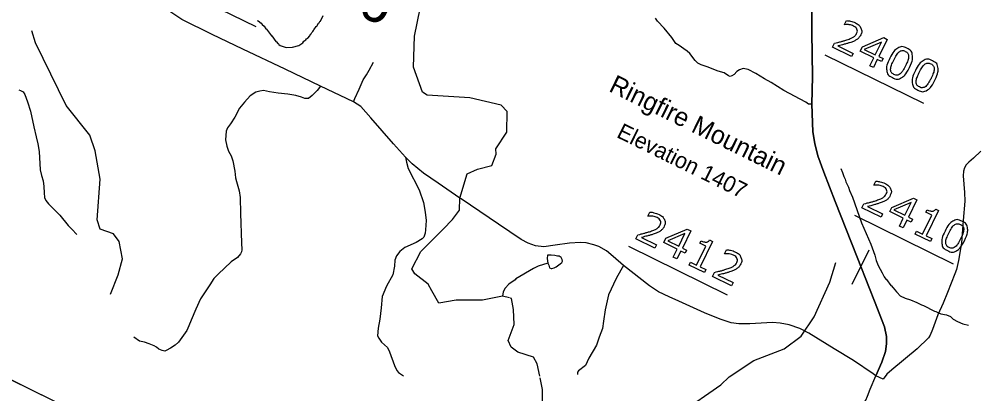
# Model space of a CAD drawing. Extents: x 1428428 to 1430511, y 857911 to 859585.
# Drawn here: x 1429036.9 to 1429265.4, y 859219.8 to 859309.5 of the extents above; entities that cross this region are included whole.
import ezdxf

# ---------------------------------------------------------------- set-up
doc = ezdxf.new("R2010")
doc.units = 0
for name, color, linetype in [('Default', 7, 'Continuous'), ('Exist Hydrographic Creek Single Shore', 7, 'Continuous'), ('Exist Hydrographic Misc Water Feature', 7, 'Continuous'), ('Exist Road Non-System Type 51', 7, 'Continuous'), ('Exist Road Secondary Type 51 Attributed', 7, 'Continuous'), ('Sheet Data Field CELL', 7, 'Continuous'), ('Sheet Title CELL', 7, 'Continuous')]:
    doc.layers.add(name, color=color, linetype=linetype)

msp = doc.modelspace()

# ---------------------------------------------------------------- linework, layer by layer
at = {"layer": 'Default'}
for p, q in [((1429069.85, 859319.28), (1429093.43, 859307.68)), ((1429229.5, 859300.92), (1429253.07, 859289.32)), ((1429236.58, 859262.53), (1429260.15, 859250.93)), ((1429182.53, 859255.12), (1429206.11, 859243.52)), ((1429239.98, 859254.23), (1429235.94, 859246.01))]:
    msp.add_line(p, q, dxfattribs=at)
for points in [[(1429234.21, 859308.12), (1429234.16, 859308.14), (1429234.63, 859309.09)], [(1429235.85, 859300.48), (1429231.29, 859302.72), (1429231.76, 859303.67)], [(1429232.61, 859303.04), (1429236.23, 859301.26), (1429235.85, 859300.48)], [(1429243.03, 859299.29), (1429242.03, 859299.79), (1429241.1, 859297.89), (1429240.23, 859298.32), (1429241.17, 859300.21), (1429237.94, 859301.8), (1429238.45, 859302.84), (1429243.58, 859305.03), (1429244.41, 859304.62), (1429242.39, 859300.51), (1429243.39, 859300.02), (1429243.03, 859299.29)], [(1429241.52, 859300.94), (1429243.02, 859303.98), (1429238.91, 859302.22), (1429241.52, 859300.94)], [(1429241.28, 859269.73), (1429241.23, 859269.75), (1429241.7, 859270.7)], [(1429250.1, 859260.9), (1429249.1, 859261.39), (1429248.17, 859259.5), (1429247.3, 859259.92), (1429248.24, 859261.82), (1429245.01, 859263.41), (1429245.52, 859264.44), (1429250.65, 859266.64), (1429251.48, 859266.23), (1429249.46, 859262.12), (1429250.46, 859261.63), (1429250.1, 859260.9)], [(1429242.92, 859262.08), (1429238.36, 859264.32), (1429238.83, 859265.28)], [(1429239.68, 859264.64), (1429243.3, 859262.86), (1429242.92, 859262.08)], [(1429248.59, 859262.54), (1429250.09, 859265.58), (1429245.98, 859263.83), (1429248.59, 859262.54)], [(1429187.24, 859262.32), (1429187.19, 859262.34), (1429187.66, 859263.29)], [(1429254.73, 859256.27), (1429251.09, 859258.06), (1429251.43, 859258.75), (1429252.83, 859258.06), (1429255.05, 859262.57), (1429253.65, 859263.26), (1429253.95, 859263.87)], [(1429255.98, 859264.04), (1429256.68, 859263.7), (1429253.7, 859257.63), (1429255.07, 859256.96), (1429254.73, 859256.27)], [(1429188.88, 859254.67), (1429184.32, 859256.92), (1429184.79, 859257.87)], [(1429196.06, 859253.49), (1429195.06, 859253.98), (1429194.13, 859252.09), (1429193.26, 859252.51), (1429194.19, 859254.41), (1429190.97, 859256), (1429191.48, 859257.04), (1429196.61, 859259.23), (1429197.44, 859258.82), (1429195.42, 859254.71), (1429196.42, 859254.22), (1429196.06, 859253.49)], [(1429194.55, 859255.14), (1429196.05, 859258.17), (1429191.94, 859256.42), (1429194.55, 859255.14)], [(1429185.64, 859257.24), (1429189.26, 859255.45), (1429188.88, 859254.67)], [(1429200.69, 859248.86), (1429197.05, 859250.65), (1429197.39, 859251.34), (1429198.79, 859250.65), (1429201.01, 859255.16), (1429199.6, 859255.85), (1429199.91, 859256.46)], [(1429201.94, 859256.63), (1429202.64, 859256.29), (1429199.65, 859250.22), (1429201.03, 859249.55), (1429200.69, 859248.86)], [(1429205.53, 859253.31), (1429205.49, 859253.34), (1429205.95, 859254.28)], [(1429207.17, 859245.67), (1429202.61, 859247.91), (1429203.08, 859248.87)], [(1429203.93, 859248.23), (1429207.56, 859246.45), (1429207.17, 859245.67)]]:
    msp.add_lwpolyline(points, dxfattribs=at)
for points in [[(1429231.76, 859303.67), (1429232.43, 859303.84), (1429233.11, 859304.01), (1429233.79, 859304.19), (1429234.4, 859304.39), (1429235.68, 859304.8), (1429236.25, 859305.13), (1429236.81, 859305.47), (1429237.09, 859306.04), (1429237.35, 859306.57), (1429237.15, 859307.03), (1429236.95, 859307.5), (1429236.33, 859307.81), (1429235.92, 859308.01), (1429235.36, 859308.1), (1429234.81, 859308.19), (1429234.21, 859308.12)], [(1429234.63, 859309.09), (1429235.03, 859309.09), (1429235.63, 859308.96), (1429236.23, 859308.82), (1429236.73, 859308.58), (1429237.77, 859308.07), (1429238.11, 859307.28), (1429238.45, 859306.49), (1429238.03, 859305.64), (1429237.84, 859305.25), (1429237.58, 859304.97), (1429237.32, 859304.68), (1429236.99, 859304.48), (1429236.67, 859304.29), (1429236.3, 859304.13), (1429235.93, 859303.98), (1429235.43, 859303.82), (1429234.71, 859303.58), (1429233.98, 859303.39), (1429233.24, 859303.2), (1429232.61, 859303.04)], [(1429249.69, 859297.85), (1429248.8, 859296.03), (1429247.82, 859295.46), (1429246.83, 859294.89), (1429245.64, 859295.48), (1429244.43, 859296.08), (1429244.29, 859297.21), (1429244.16, 859298.35), (1429245.04, 859300.13), (1429245.92, 859301.93), (1429246.91, 859302.51), (1429247.89, 859303.09), (1429249.09, 859302.5), (1429250.3, 859301.9), (1429250.43, 859300.75), (1429250.56, 859299.61), (1429249.69, 859297.85)], [(1429247.49, 859296.38), (1429247.83, 859296.67), (1429248.13, 859297.14), (1429248.43, 859297.6), (1429248.78, 859298.3), (1429249.11, 859298.99), (1429249.31, 859299.52), (1429249.5, 859300.06), (1429249.51, 859300.49), (1429249.52, 859300.92), (1429249.34, 859301.23), (1429249.15, 859301.54), (1429248.72, 859301.75), (1429248.3, 859301.96), (1429247.93, 859301.92), (1429247.57, 859301.88), (1429247.23, 859301.6), (1429246.91, 859301.34), (1429246.59, 859300.83), (1429246.27, 859300.32), (1429245.95, 859299.68), (1429245.61, 859298.97), (1429245.42, 859298.47), (1429245.24, 859297.97), (1429245.22, 859297.52), (1429245.19, 859297.09), (1429245.37, 859296.77), (1429245.55, 859296.45), (1429246.01, 859296.23), (1429246.43, 859296.02), (1429246.8, 859296.06), (1429247.16, 859296.1), (1429247.49, 859296.38)], [(1429255.79, 859294.85), (1429254.9, 859293.03), (1429253.91, 859292.46), (1429252.93, 859291.89), (1429251.74, 859292.48), (1429250.53, 859293.08), (1429250.39, 859294.21), (1429250.26, 859295.34), (1429251.13, 859297.13), (1429252.02, 859298.92), (1429253.01, 859299.5), (1429253.99, 859300.08), (1429255.19, 859299.5), (1429256.4, 859298.9), (1429256.53, 859297.75), (1429256.66, 859296.61), (1429255.79, 859294.85)], [(1429253.59, 859293.38), (1429253.93, 859293.67), (1429254.23, 859294.13), (1429254.53, 859294.6), (1429254.87, 859295.3), (1429255.21, 859295.99), (1429255.41, 859296.52), (1429255.6, 859297.06), (1429255.61, 859297.49), (1429255.62, 859297.92), (1429255.44, 859298.23), (1429255.25, 859298.54), (1429254.82, 859298.75), (1429254.4, 859298.96), (1429254.03, 859298.92), (1429253.67, 859298.88), (1429253.33, 859298.6), (1429253.01, 859298.34), (1429252.69, 859297.83), (1429252.37, 859297.32), (1429252.05, 859296.68), (1429251.7, 859295.97), (1429251.52, 859295.47), (1429251.34, 859294.97), (1429251.31, 859294.52), (1429251.29, 859294.09), (1429251.47, 859293.77), (1429251.65, 859293.45), (1429252.1, 859293.23), (1429252.53, 859293.02), (1429252.9, 859293.06), (1429253.26, 859293.1), (1429253.59, 859293.38)], [(1429238.83, 859265.28), (1429239.5, 859265.45), (1429240.18, 859265.62), (1429240.86, 859265.79), (1429241.47, 859265.99), (1429242.75, 859266.4), (1429243.32, 859266.74), (1429243.88, 859267.08), (1429244.17, 859267.65), (1429244.42, 859268.17), (1429244.22, 859268.64), (1429244.02, 859269.11), (1429243.4, 859269.41), (1429242.99, 859269.62), (1429242.43, 859269.71), (1429241.88, 859269.8), (1429241.28, 859269.73)], [(1429241.7, 859270.7), (1429242.1, 859270.7), (1429242.7, 859270.56), (1429243.3, 859270.43), (1429243.8, 859270.18), (1429244.84, 859269.67), (1429245.18, 859268.88), (1429245.52, 859268.1), (1429245.1, 859267.24), (1429244.92, 859266.86), (1429244.65, 859266.57), (1429244.39, 859266.29), (1429244.06, 859266.09), (1429243.74, 859265.89), (1429243.37, 859265.74), (1429243, 859265.58), (1429242.5, 859265.42), (1429241.78, 859265.19), (1429241.05, 859264.99), (1429240.31, 859264.8), (1429239.68, 859264.64)], [(1429184.79, 859257.87), (1429185.46, 859258.04), (1429186.14, 859258.21), (1429186.82, 859258.38), (1429187.43, 859258.58), (1429188.71, 859258.99), (1429189.28, 859259.33), (1429189.84, 859259.67), (1429190.12, 859260.24), (1429190.38, 859260.77), (1429190.18, 859261.23), (1429189.98, 859261.7), (1429189.36, 859262), (1429188.94, 859262.21), (1429188.39, 859262.3), (1429187.84, 859262.39), (1429187.24, 859262.32)], [(1429187.66, 859263.29), (1429188.06, 859263.29), (1429188.66, 859263.15), (1429189.26, 859263.02), (1429189.76, 859262.77), (1429190.8, 859262.26), (1429191.14, 859261.48), (1429191.48, 859260.69), (1429191.06, 859259.83), (1429190.87, 859259.45), (1429190.61, 859259.17), (1429190.35, 859258.88), (1429190.01, 859258.68), (1429189.7, 859258.48), (1429189.33, 859258.33), (1429188.96, 859258.18), (1429188.46, 859258.01), (1429187.74, 859257.78), (1429187.01, 859257.59), (1429186.27, 859257.39), (1429185.64, 859257.24)], [(1429253.95, 859263.87), (1429254.23, 859263.73), (1429254.58, 859263.62), (1429254.93, 859263.51), (1429255.14, 859263.52), (1429255.41, 859263.53), (1429255.61, 859263.64), (1429255.82, 859263.76), (1429255.98, 859264.04)], [(1429262.86, 859256.45), (1429261.97, 859254.64), (1429260.99, 859254.07), (1429260, 859253.5), (1429258.81, 859254.09), (1429257.6, 859254.68), (1429257.46, 859255.82), (1429257.33, 859256.95), (1429258.21, 859258.73), (1429259.09, 859260.53), (1429260.08, 859261.11), (1429261.06, 859261.69), (1429262.26, 859261.1), (1429263.47, 859260.51), (1429263.6, 859259.36), (1429263.73, 859258.21), (1429262.86, 859256.45)], [(1429260.66, 859254.98), (1429261, 859255.27), (1429261.3, 859255.74), (1429261.6, 859256.21), (1429261.95, 859256.9), (1429262.28, 859257.59), (1429262.48, 859258.13), (1429262.67, 859258.66), (1429262.68, 859259.09), (1429262.69, 859259.52), (1429262.51, 859259.83), (1429262.32, 859260.14), (1429261.89, 859260.35), (1429261.47, 859260.56), (1429261.1, 859260.52), (1429260.74, 859260.48), (1429260.4, 859260.21), (1429260.08, 859259.95), (1429259.76, 859259.44), (1429259.44, 859258.92), (1429259.12, 859258.28), (1429258.78, 859257.58), (1429258.59, 859257.08), (1429258.41, 859256.58), (1429258.38, 859256.12), (1429258.36, 859255.7), (1429258.54, 859255.38), (1429258.72, 859255.06), (1429259.18, 859254.83), (1429259.6, 859254.62), (1429259.97, 859254.66), (1429260.33, 859254.7), (1429260.66, 859254.98)], [(1429199.91, 859256.46), (1429200.19, 859256.32), (1429200.54, 859256.21), (1429200.89, 859256.1), (1429201.1, 859256.11), (1429201.36, 859256.12), (1429201.57, 859256.23), (1429201.78, 859256.35), (1429201.94, 859256.63)], [(1429203.08, 859248.87), (1429203.76, 859249.04), (1429204.44, 859249.21), (1429205.11, 859249.38), (1429205.72, 859249.58), (1429207.01, 859249.99), (1429207.57, 859250.33), (1429208.14, 859250.66), (1429208.42, 859251.24), (1429208.68, 859251.76), (1429208.48, 859252.23), (1429208.27, 859252.7), (1429207.65, 859253), (1429207.24, 859253.2), (1429206.69, 859253.3), (1429206.14, 859253.39), (1429205.53, 859253.31)], [(1429205.95, 859254.28), (1429206.35, 859254.28), (1429206.95, 859254.15), (1429207.55, 859254.02), (1429208.06, 859253.77), (1429209.09, 859253.26), (1429209.44, 859252.47), (1429209.78, 859251.68), (1429209.36, 859250.83), (1429209.17, 859250.45), (1429208.91, 859250.16), (1429208.65, 859249.88), (1429208.31, 859249.67), (1429208, 859249.48), (1429207.63, 859249.33), (1429207.26, 859249.17), (1429206.75, 859249.01), (1429206.04, 859248.77), (1429205.3, 859248.58), (1429204.57, 859248.39), (1429203.93, 859248.23)]]:
    msp.add_open_spline(points, degree=3, dxfattribs=at)
at = {"layer": 'Exist Hydrographic Creek Single Shore'}
for points in [[(1429142.24, 859266.66), (1429143.99, 859272.42), (1429146.47, 859273.58), (1429149.91, 859274.45), (1429150.91, 859277.12), (1429150.87, 859278.47), (1429153.46, 859282.38), (1429153.58, 859287.34), (1429152.09, 859288.85), (1429144.6, 859290.66), (1429134.41, 859291.27), (1429133.27, 859292.01), (1429131.12, 859298), (1429131.37, 859305.4), (1429132.73, 859312.02), (1429138.15, 859322.52), (1429140.73, 859325.69), (1429140.77, 859325.72)], [(1429154.07, 859242.79), (1429152.45, 859243.17), (1429147.63, 859242.2), (1429141.36, 859242.24), (1429137.19, 859241.51), (1429135.57, 859244.48), (1429134.69, 859246.04), (1429131.45, 859248.53), (1429130.79, 859249.76), (1429132.93, 859253.9), (1429138.25, 859259.19), (1429140.45, 859261.56), (1429142.19, 859263.76), (1429142.24, 859266.66)], [(1429167.35, 859199.95), (1429161.59, 859203.67), (1429160.48, 859205.14), (1429160.01, 859208.63), (1429158.99, 859210.63), (1429161.98, 859217.51), (1429162.03, 859220.88), (1429161.44, 859223.64)]]:
    msp.add_lwpolyline(points, dxfattribs=at)
at = {"layer": 'Exist Hydrographic Misc Water Feature'}
for points in [[(1429093.77, 859309.16), (1429094.06, 859309.01), (1429094.77, 859308.46), (1429094.97, 859308.18), (1429095.47, 859307.74), (1429095.89, 859307.16), (1429096.03, 859307.09), (1429097.19, 859305.49), (1429097.33, 859305.42), (1429098.27, 859304.12), (1429098.41, 859304.04), (1429098.73, 859303.61), (1429098.87, 859303.54), (1429098.99, 859303.38), (1429099.32, 859303.17), (1429100.75, 859302.65), (1429102.26, 859302.77), (1429103.73, 859303.17), (1429104.67, 859303.77), (1429104.96, 859304.16), (1429105.39, 859304.47), (1429105.58, 859304.74), (1429105.9, 859304.93), (1429106.34, 859305.42), (1429106.56, 859305.85), (1429106.7, 859305.95), (1429106.87, 859306.27), (1429107.07, 859306.49), (1429107.22, 859306.77), (1429107.36, 859306.87), (1429107.87, 859307.69), (1429108.02, 859307.79), (1429108.46, 859308.47), (1429108.6, 859308.57), (1429108.75, 859308.86), (1429108.9, 859308.96), (1429109.59, 859310.3)], [(1429058.76, 859243.64), (1429060.59, 859248.31), (1429061.63, 859252.13), (1429060.77, 859256.27), (1429059.47, 859258.13), (1429056.27, 859259.19), (1429055.54, 859261.42), (1429056.26, 859271.17), (1429055.09, 859277.98), (1429053.81, 859281.68), (1429048.09, 859288.77), (1429040.83, 859303.76), (1429039.9, 859306.68)], [(1429233.29, 859273.73), (1429233.7, 859272.79), (1429234.01, 859271.82), (1429234.32, 859271.21), (1429234.53, 859270.56), (1429235.17, 859269.28), (1429235.42, 859268.47), (1429236.13, 859266.88), (1429238.23, 859260.7), (1429240.46, 859255.62), (1429241.4, 859253.04), (1429241.76, 859251.7), (1429242.23, 859250.51), (1429243.18, 859248.79), (1429243.63, 859247.84), (1429244.05, 859247.26), (1429244.19, 859247.19), (1429245.24, 859245.74), (1429245.39, 859245.66), (1429245.7, 859245.23), (1429245.84, 859245.16), (1429246.62, 859244.21), (1429246.77, 859244.09), (1429247.49, 859243.31), (1429248.7, 859242.68), (1429250, 859242.3), (1429251.44, 859241.71), (1429252.57, 859241.12), (1429253.04, 859240.97), (1429255.73, 859239.57), (1429256.05, 859239.49), (1429256.62, 859239.19), (1429257.22, 859238.97), (1429258.54, 859238.73), (1429259.5, 859238.33), (1429260.19, 859237.7), (1429261.2, 859237.11), (1429262.44, 859236.56), (1429263.81, 859236.27)], [(1429163.3, 859251.1), (1429163.49, 859250.65), (1429163.69, 859250.01), (1429164.04, 859249.82), (1429164.22, 859249.82), (1429164.78, 859249.94), (1429165.23, 859250.2), (1429166.24, 859250.93), (1429166.6, 859251.28), (1429166.75, 859251.57), (1429166.72, 859251.94), (1429166.48, 859252.43), (1429165.95, 859252.8), (1429165.59, 859252.8), (1429164.95, 859252.96), (1429164.09, 859253.04), (1429163.17, 859253), (1429163.08, 859252.21), (1429163.3, 859251.1)], [(1429163.3, 859251.1), (1429160.94, 859250.35), (1429159.86, 859249.83), (1429155.64, 859247.34), (1429155.42, 859247.09), (1429153.97, 859246.04), (1429153.03, 859245.09), (1429152.59, 859244.24), (1429152.45, 859243.17)], [(1429167.35, 859199.95), (1429168.85, 859202.13), (1429170.89, 859203.15), (1429172.46, 859203.3), (1429173.89, 859202.77), (1429177.99, 859203.09), (1429180.09, 859204.23), (1429188.61, 859212.38), (1429194.99, 859215.29), (1429204.63, 859221.98), (1429206.59, 859223.92), (1429212.53, 859227.8), (1429219.8, 859230.61), (1429223.81, 859233.64), (1429226.92, 859238.24), (1429230.66, 859246.57), (1429232.15, 859251.27)], [(1429161.34, 859224.1), (1429160.71, 859227.04), (1429159.83, 859228.6), (1429156.13, 859229.78), (1429154.5, 859230.99), (1429153.82, 859232.6), (1429155.25, 859236.38), (1429155.08, 859240.01), (1429154.58, 859242.66), (1429154.23, 859242.75)]]:
    msp.add_lwpolyline(points, dxfattribs=at)
at = {"layer": 'Exist Road Non-System Type 51'}
for points in [[(1429225.57, 859289.11), (1429224.95, 859289.56), (1429219.68, 859292.37), (1429216.68, 859294.29), (1429215.06, 859295.15), (1429212.97, 859296.48), (1429211.12, 859297.39), (1429209.93, 859297.64), (1429209.08, 859297.33), (1429208.43, 859296.89), (1429207.78, 859296.25), (1429207.27, 859295.88), (1429206.86, 859295.72), (1429206.42, 859295.93), (1429205.45, 859296.63), (1429204, 859297.02), (1429201.35, 859298.03), (1429199.9, 859298.49), (1429199.14, 859298.9), (1429198.52, 859299.57), (1429197.23, 859301.26), (1429196.61, 859301.78), (1429195.76, 859302.35), (1429194.67, 859303.11), (1429193.9, 859303.63), (1429192.93, 859305.06), (1429191.07, 859307.29), (1429189.47, 859308.95), (1429189, 859309.7)], [(1429116.78, 859289.64), (1429117.1, 859290.51), (1429118.14, 859292.73), (1429119.12, 859294.93), (1429119.94, 859296.17), (1429120.54, 859297.28), (1429121.58, 859299.17)], [(1429036.78, 859292.55), (1429037.23, 859292.38), (1429037.81, 859292.05), (1429038.24, 859291.41), (1429038.88, 859289.71), (1429039.58, 859287.46), (1429040.37, 859283.67), (1429040.92, 859281.33), (1429041.33, 859279.59), (1429041.7, 859277.76), (1429041.9, 859273.42), (1429042.23, 859272.04), (1429042.66, 859270.76), (1429042.82, 859269.39), (1429042.89, 859267.92), (1429042.98, 859266.81), (1429043.27, 859266.09), (1429043.89, 859265.3), (1429046.63, 859262.58), (1429048.58, 859260.08), (1429049.5, 859259.25), (1429050.68, 859257.98)], [(1429108.91, 859293.45), (1429108.13, 859292.39), (1429106.93, 859291.17), (1429106.06, 859290.51), (1429105.18, 859290.5), (1429104.39, 859290.78), (1429103.05, 859291.17), (1429101.1, 859291.53), (1429098.81, 859291.78), (1429096.73, 859292.09), (1429095.28, 859292.37), (1429094.4, 859292.25), (1429093.44, 859291.96), (1429092.13, 859291.08), (1429090.76, 859289.59), (1429089.6, 859288.13), (1429088.41, 859286.04), (1429087.41, 859284.45), (1429086.71, 859283.48), (1429086.41, 859282.64), (1429086.2, 859280.56), (1429086.5, 859279.07), (1429086.97, 859277.91), (1429087.57, 859276.79), (1429087.99, 859275.54), (1429088.43, 859273.09), (1429088.63, 859271.51), (1429088.86, 859270.63), (1429089.51, 859268.4), (1429089.71, 859266.82), (1429089.83, 859262.94), (1429090.01, 859255.98), (1429090.1, 859254.29), (1429090.04, 859253.83), (1429089.78, 859253.3), (1429089.08, 859252.44), (1429087.58, 859251.38)], [(1429226.4, 859289.11), (1429225.57, 859289.11)], [(1429129.22, 859276.44), (1429129.46, 859275.21), (1429129.91, 859273.72), (1429132.5, 859268.6), (1429133.55, 859265.58), (1429133.93, 859263.27), (1429134.22, 859261.29), (1429134.05, 859259.06), (1429133.91, 859258.28), (1429133.62, 859257.27), (1429133.2, 859256.91), (1429131.76, 859256.06), (1429129.11, 859254.83), (1429127.87, 859253.88), (1429127.07, 859252.85), (1429126.66, 859251.78), (1429126.59, 859250.38), (1429126.23, 859248.31), (1429124.7, 859245.62), (1429123.64, 859243.14), (1429123.4, 859240.4), (1429123.07, 859237.73), (1429122.72, 859235.53), (1429122.57, 859233.73), (1429122.83, 859233.19), (1429123.51, 859232.16), (1429124.93, 859230.89), (1429125.43, 859229.85), (1429126.62, 859226.61), (1429127.18, 859225.43), (1429127.58, 859224.91), (1429128.78, 859224.15)], [(1429087.58, 859251.38), (1429084.48, 859248.48), (1429083.45, 859247.39), (1429082.44, 859245.92), (1429080.22, 859242.56), (1429079.1, 859240.12), (1429078, 859237.46), (1429077.45, 859236.09), (1429076.96, 859235.02), (1429075, 859232.18), (1429074.16, 859231.49), (1429073.05, 859230.73), (1429072.07, 859230.23), (1429071.71, 859230.08), (1429071.07, 859230.19), (1429070.31, 859230.56), (1429069.72, 859231.02), (1429069.13, 859231.31), (1429067.99, 859231.83), (1429066.82, 859232.2), (1429065.69, 859232.47), (1429064.27, 859233.38)], [(1429181.39, 859250.52), (1429180.68, 859249.38), (1429179.59, 859247.42), (1429177.74, 859243.5), (1429176.94, 859239.89), (1429176.59, 859237.18), (1429176.34, 859235.5), (1429175.56, 859233.43), (1429174.88, 859231.47), (1429173.07, 859228.36), (1429172.26, 859226.64), (1429170.56, 859225.35), (1429170.39, 859224.99), (1429170.33, 859224.46)]]:
    msp.add_lwpolyline(points, dxfattribs=at)
at = {"layer": 'Exist Road Secondary Type 51 Attributed'}
for points in [[(1429241.66, 859224.11), (1429243.1, 859227.39), (1429244.02, 859229.95), (1429244.26, 859231.8), (1429244.2, 859233.55), (1429243.77, 859235.85), (1429241.37, 859242.04), (1429240.13, 859245.01), (1429237.24, 859252.56), (1429231.94, 859265.82), (1429229.21, 859272.84), (1429227.81, 859276.72), (1429227.1, 859279.68), (1429226.65, 859282.51), (1429226.4, 859289.11), (1429226.52, 859295.74), (1429226.35, 859306.35), (1429226.4, 859317.36)], [(1429142.24, 859266.66), (1429137.03, 859270.21), (1429133.52, 859272.61), (1429130.85, 859274.84), (1429129.22, 859276.44), (1429126.37, 859279.65), (1429120.98, 859285.82), (1429118.57, 859288.52), (1429116.78, 859289.64), (1429108.91, 859293.45), (1429100.47, 859297.45), (1429090.35, 859302.27), (1429083, 859305.77), (1429075.8, 859309.33), (1429072.69, 859311.42)], [(1429266.77, 859277.88), (1429265.01, 859276.17), (1429263.93, 859275.28), (1429263.3, 859274.62), (1429262.88, 859273.9), (1429262.6, 859273.08), (1429262.54, 859272.01), (1429262.86, 859267.95), (1429262.95, 859265.88), (1429262.58, 859261.33), (1429262.15, 859255.93), (1429261.87, 859254.04), (1429261.46, 859251.73), (1429260.96, 859249.58), (1429260.58, 859248.5), (1429258.84, 859244.1), (1429257.8, 859241.55), (1429256.52, 859238.76), (1429255.23, 859235.26), (1429254.63, 859233.85), (1429254.27, 859233.25), (1429251.56, 859230.6), (1429245.48, 859225.54), (1429244.34, 859224.52), (1429243.44, 859223.33)], [(1429241.66, 859224.11), (1429241, 859224.59), (1429236.33, 859227.78), (1429231.71, 859230.6), (1429225.66, 859234.35), (1429223.53, 859235.43), (1429220.98, 859236.35), (1429218.82, 859236.7), (1429217, 859236.86), (1429211.55, 859236.58), (1429208.9, 859236.56), (1429207.1, 859236.83), (1429204.44, 859237.71), (1429200.74, 859239.23), (1429194.59, 859242.01), (1429192.26, 859243), (1429189.7, 859244.27), (1429187.6, 859245.67), (1429181.39, 859250.52), (1429178.92, 859252.72), (1429177.26, 859254.03), (1429175.46, 859255.04), (1429174.27, 859255.5), (1429172.46, 859255.99), (1429171.08, 859256.05), (1429168.44, 859255.89), (1429165.06, 859255.38), (1429162.35, 859254.97), (1429160.35, 859255.21), (1429158.56, 859255.88), (1429156.88, 859256.77), (1429151.45, 859260.39), (1429142.56, 859266.44), (1429142.24, 859266.66)], [(1429211.26, 859178.44), (1429214.27, 859181.53), (1429217.69, 859185.07), (1429219.11, 859186.83), (1429220.86, 859189.27), (1429225.99, 859197.44), (1429230.28, 859204.36), (1429233.41, 859208.93), (1429236.36, 859213.61), (1429238.11, 859216.32), (1429239.29, 859218.34), (1429239.68, 859219.31), (1429240.32, 859220.99), (1429241.66, 859224.11)], [(1429243.44, 859223.33), (1429241.66, 859224.11)]]:
    msp.add_lwpolyline(points, dxfattribs=at)
at = {"layer": 'Sheet Title CELL'}
msp.add_line((1429228.53, 859127.93), (1428950.38, 859264.79), dxfattribs=at)
for points in [[(1429226.4, 859317.36), (1429226.35, 859306.35), (1429226.52, 859295.74), (1429226.4, 859289.11), (1429226.65, 859282.51), (1429227.1, 859279.68), (1429227.81, 859276.72), (1429229.21, 859272.84), (1429231.94, 859265.82), (1429237.24, 859252.56), (1429240.13, 859245.01), (1429241.37, 859242.04), (1429243.77, 859235.85), (1429244.2, 859233.55), (1429244.26, 859231.8), (1429244.02, 859229.95), (1429243.1, 859227.39), (1429241.66, 859224.11)], [(1429142.24, 859266.66), (1429137.03, 859270.21), (1429133.52, 859272.61), (1429130.85, 859274.84), (1429129.22, 859276.44), (1429126.37, 859279.65), (1429120.98, 859285.82), (1429118.57, 859288.52), (1429116.78, 859289.64), (1429108.91, 859293.45), (1429100.47, 859297.45), (1429090.35, 859302.27), (1429083, 859305.77), (1429075.8, 859309.33), (1429072.69, 859311.42)], [(1429241.66, 859224.11), (1429241, 859224.59), (1429236.33, 859227.78), (1429231.71, 859230.6), (1429225.66, 859234.35), (1429223.53, 859235.43), (1429220.98, 859236.35), (1429218.82, 859236.7), (1429217, 859236.86), (1429211.55, 859236.58), (1429208.9, 859236.56), (1429207.1, 859236.83), (1429204.44, 859237.71), (1429200.74, 859239.23), (1429194.59, 859242.01), (1429192.26, 859243), (1429189.7, 859244.27), (1429187.6, 859245.67), (1429181.39, 859250.52), (1429178.92, 859252.72), (1429177.26, 859254.03), (1429175.46, 859255.04), (1429174.27, 859255.5), (1429172.46, 859255.99), (1429171.08, 859256.05), (1429168.44, 859255.89), (1429165.06, 859255.38), (1429162.35, 859254.97), (1429160.35, 859255.21), (1429158.56, 859255.88), (1429156.88, 859256.77), (1429151.45, 859260.39), (1429142.56, 859266.44), (1429142.24, 859266.66)]]:
    msp.add_lwpolyline(points, dxfattribs=at)
msp.add_lwpolyline([(1428950.38, 859264.79), (1429228.53, 859127.93), (1429213.05, 859096.45), (1428934.9, 859233.32)], close=True, dxfattribs=at)

# ---------------------------------------------------------------- texts
at = {"layer": 'Default'}
for s, height, p in [('B-4846', 10, (1429085.12, 859326.62)), ('Ringfire Mountain', 4.4, (1429177.62, 859292.33)), ('Elevation 1407', 3.8, (1429179.49, 859281.31))]:
    msp.add_text(s, height=height, rotation=333.8001, dxfattribs=at).set_placement(p)
at = {"layer": 'Sheet Data Field CELL'}
msp.add_text('VICINITY MAP', height=20, rotation=333.8001, dxfattribs=at).set_placement((1428981.76, 859220.73))

doc.saveas('drawing.dxf')
